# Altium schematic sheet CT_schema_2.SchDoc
size 276 x 169 mm
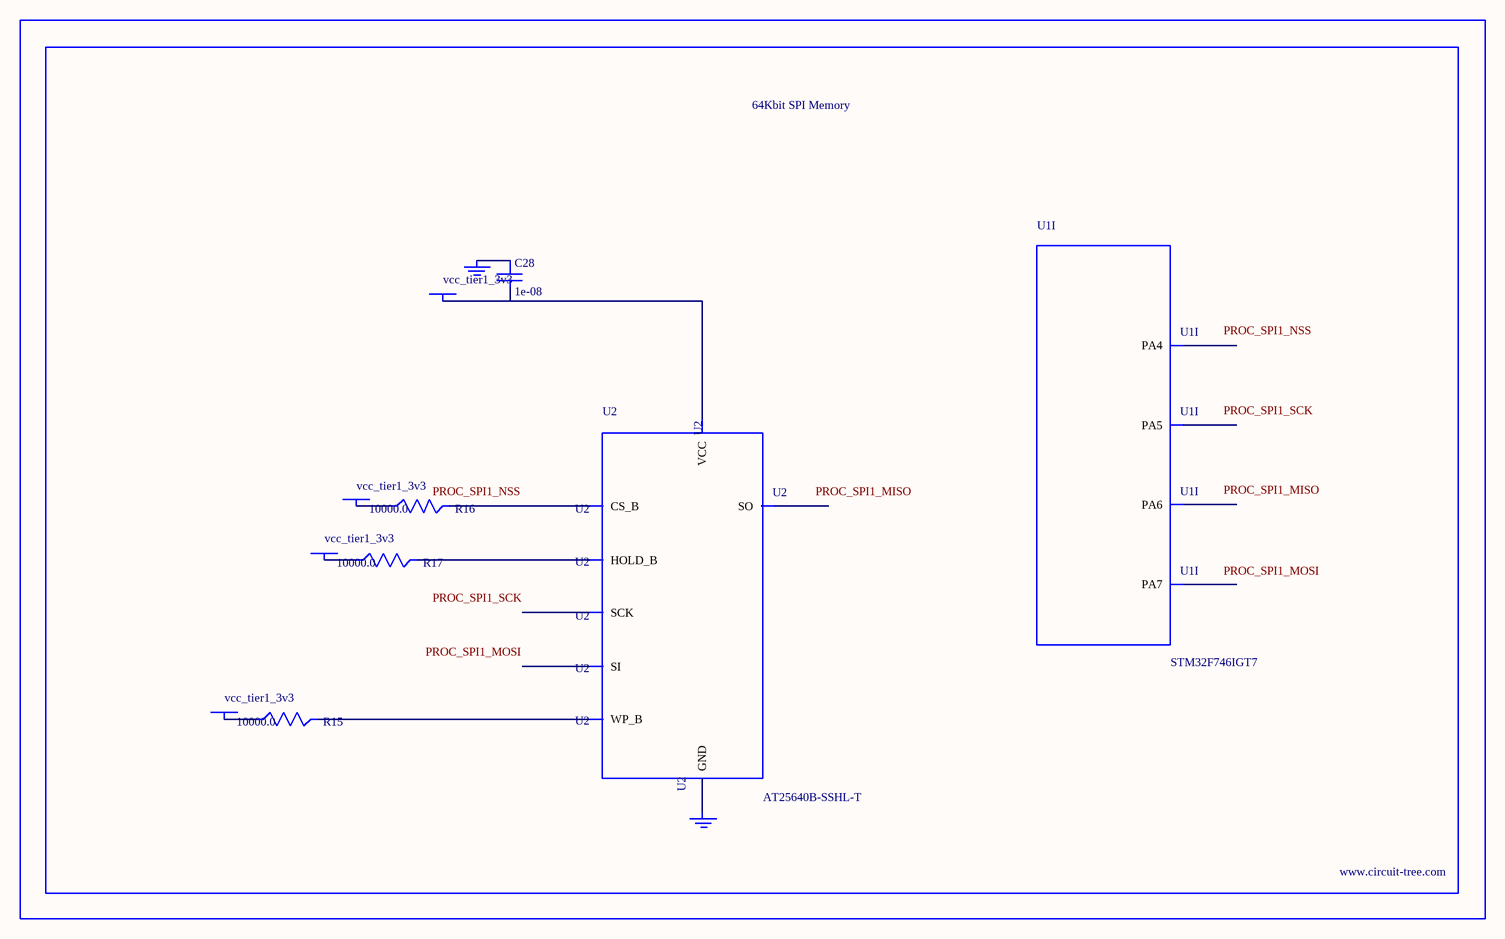
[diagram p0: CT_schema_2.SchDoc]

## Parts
BORDER1  (no value)
C28  1e-08  [C0402]
GND_INSTANCE_1_0  (no value)
GND_INSTANCE_1_1  (no value)
POWER_INSTANCE_1_0  vcc_tier1_3v3
POWER_INSTANCE_1_1  vcc_tier1_3v3
POWER_INSTANCE_1_2  vcc_tier1_3v3
POWER_INSTANCE_1_3  vcc_tier1_3v3
R15  10000.0  [R0603]
R16  10000.0  [R0603]
R17  10000.0  [R0603]
U1  STM32F746IGT7  [LQFP176]  (part I of 15)
U2  AT25640B-SSHL-T  [SOIC-8]

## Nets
NetC28_1: C28.1 GND_INSTANCE_1_0.0(GND)
NetC28_2: C28.2 POWER_INSTANCE_1_3.0(PWR) U2.8(VCC)
NetGND_INSTANCE_1_1_0: GND_INSTANCE_1_1.0(GND) U2.4(GND)
NetPOWER_INSTANCE_1_0_0: POWER_INSTANCE_1_0.0(PWR) R16.1
NetPOWER_INSTANCE_1_1_0: POWER_INSTANCE_1_1.0(PWR) R15.1
NetPOWER_INSTANCE_1_2_0: POWER_INSTANCE_1_2.0(PWR) R17.1
NetR15_2: R15.2 U2.3(WP_B)
NetR16_2: R16.2 U2.1(CS_B)
NetR17_2: R17.2 U2.7(HOLD_B)

Not connected (* = marked no-connect by the designer): U1 50(PA4) 51(PA5) 52(PA6) 53(PA7); U2 2(SO) 5(SI) 6(SCK)

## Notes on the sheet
- Labels drawn without touching a wire or pin: PROC_SPI1_MISO, PROC_SPI1_MOSI, PROC_SPI1_NSS, PROC_SPI1_SCK

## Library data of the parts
BORDER1 = BORDER_PAGE1
C28 = C0402C103K3RAC
GND_INSTANCE_1_0 GND_INSTANCE_1_1 = GND
POWER_INSTANCE_1_0-POWER_INSTANCE_1_3 = PWR
R15-R17 = RC0603JR-0710KL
